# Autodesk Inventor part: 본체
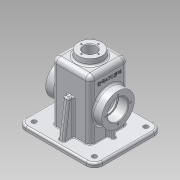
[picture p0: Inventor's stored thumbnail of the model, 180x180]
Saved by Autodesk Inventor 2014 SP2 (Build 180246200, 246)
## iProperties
Created: 2016-08
Part Number: 본체
Material: 알루미늄 6061
Document SubType Name: Modeling
Designer: user
Density: 2.71 g/cm^3
Appearance: 알루미늄 - 평지
Mass: 800.582 g
Surface Area: 913.686 cm^2
Volume: 295.418 cm^3
Author: user
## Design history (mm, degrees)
sketch "스케치1"
  geometry: L1 (-32.5, -32.5)-(32.5, -32.5); L2 (32.5, -32.5)-(32.5, 32.5); L3 (32.5, 32.5)-(-32.5, 32.5); L4 (-32.5, 32.5)-(-32.5, -32.5); L5 (-32.5, -32.5)-(32.5, 32.5); L6 (32.5, -32.5)-(-32.5, 32.5); 1 further point
  constraints: 12 end point, 2 midpoint, 2 parallel, 1 horizontal, 1 perpendicular
  dimensions: "d0" = 65 distance of L3.end L2.end; "d1" = 65 distance of L2.end L1.end
extrude "돌출1" new body sketch "스케치1" distance "d2" = 110; taper "d3" = 0 deg
feature "쉘1" dims "d4" = 5
sketch "스케치2"
  geometry: L1 (32.5, -32.5)-(-32.5, -32.5) reference; L2 (32.5, 32.5)-(32.5, -32.5) reference; L3 (-32.5, 32.5)-(32.5, 32.5) reference; L4 (-32.5, -32.5)-(-32.5, 32.5) reference; L5 (65, 57.5)-(-65, 57.5); L6 (-65, 57.5)-(-65, -57.5); L7 (-65, -57.5)-(65, -57.5); L8 (65, -57.5)-(65, 57.5); L9 (65, 57.5)-(-65, -57.5); L10 (-65, 57.5)-(65, -57.5); 1 further point
  constraints: 12 end point, 2 midpoint, 2 parallel, 1 horizontal, 1 perpendicular
  dimensions: "d5" = 130 distance of L7.end L6.end; "d6" = 115 distance of L6.end L5.end
extrude "돌출2" join sketch "스케치2" distance "d7" = 10; taper "d8" = 0 deg
sketch "스케치3"
  geometry: L1 (-65, -57.5)-(65, -57.5) reference; L2 (65, -57.5)-(65, 57.5) reference; L3 (65, 57.5)-(-65, 57.5) reference; L4 (-65, 57.5)-(-65, -57.5) reference; L5 (60, -52.5)-(-60, -52.5); L6 (-60, -52.5)-(-60, 52.5); L7 (-60, 52.5)-(60, 52.5); L8 (60, 52.5)-(60, -52.5); 1 further point
  constraints: 8 end point, 3 other
  dimensions: "d9" = 5 distance between parallel lines of L5 L1
extrude "돌출3" cut sketch "스케치3" distance "d10" = 3; taper "d11" = 0 deg
sketch "스케치4"
  geometry: C1 r 27.5 at (55, 32.5); 1 further point
  constraints: 1 centre point, 1 horizontal alignment
  dimensions: "d12" = 55 diameter of C1; "d13" = 55 distance of point (110, 32.5) C1.centre
extrude "돌출4" join sketch "스케치4" distance "d14" = 15; taper "d15" = 0 deg
sketch "스케치5"
  geometry: L1 (-27.5, 0)-(-27.5, 105) reference; L2 (-65, 10)-(65, 10) reference; L3 (-32.5, 27.5)-(-47.5, 27.5) reference; L4 (-42.5, 10)-(-42.5, 27.5); 1 further point
  constraints: 2 end point, 2 point on line, 1 perpendicular
  dimensions: "d16" = 15 distance from line of L4.start L1
feature "리브1" sketch "스케치5" dims "d17" = 1, "d18" = 6, "d19" = 0, "d20" = 0, "d21" = 1, "d22" = 1
sketch "스케치6" dims "d23" = 42
  geometry: C1 r 27.5 at (0, 0) reference; 3 further points
  constraints: 2 horizontal alignment, 1 coincident, 2 other
hole "구멍1" sketch "스케치6" at (-21, 0) diameter "d24" = 3.242; stored, may be unused: countersink angle "d28" = 90 deg, drill point angle "d30" = 118 deg; dims "d25" = 8, "d26" = 4, "d27" = 2, "d29" = 10
sketch "스케치7"
  geometry: L1 (57.5, 3)-(57.5, 10) reference; L2 (57.5, 10)-(-57.5, 10) reference; L3 (49.5, 10)-(41.068, 70); L4 (-52.5, 0)-(52.5, 0) reference; L5 (32.5, 10)-(32.5, 110) reference; L6 (41.068, 70)-(32.5, 70); 1 further point
  constraints: 4 end point, 2 point on line, 1 perpendicular
  dimensions: "d34" = 8 distance of L1.end L3.start; "d35" = 8 deg angle of L1 L3; "d36" = 70 distance from line of L4 L3.end
extrude "돌출5" join sketch "스케치7" stored distance "d37" = 10; taper "d38" = 0 deg
node "작업 평면1"
sketch "스케치8"
  geometry: C1 r 20 at (0, 0); 1 further point
  constraints: 1 centre point, 1 coincident
  dimensions: "d40" = 40 diameter of C1
extrude "돌출6" join sketch "스케치8" stored distance "d41" = 10; taper "d42" = 7 deg
hole "구멍2" diameter "d45" = 21; stored, may be unused: countersink angle "d49" = 90 deg, drill point angle "d51" = 118 deg; dims "d43" = 10, "d44" = 10, "d46" = 8, "d47" = 4, "d48" = 2, "d50" = 10
sketch "스케치9" dims "d52" = 29
  geometry: 3 further points
  constraints: 2 vertical alignment, 1 coincident, 2 other
hole "구멍3" sketch "스케치9" at (0, 14.5) diameter "d53" = 2.459; stored, may be unused: countersink angle "d57" = 90 deg, drill point angle "d59" = 118 deg; dims "d54" = 7, "d55" = 4, "d56" = 2, "d58" = 9
fillet "모깎기1" dims "d63" = 14
fillet "모깎기2" dims "d64" = 9
fillet "모깎기3" dims "d65" = 8
fillet "모깎기4" dims "d66" = 8
fillet "모깎기5" dims "d67" = 3
fillet "모깎기6" dims "d68" = 3
fillet "모깎기7" dims "d69" = 1
sketch "스케치11"
  geometry: L1 (-18, 4.5)-(-18, 44.5) reference; L2 (0, -8)-(91, -8) reference; 2 further points
  constraints: 1 other
  dimensions: "d73" = 32.5 distance from line of point (8, 24.5) L2; "d74" = 26 distance from line of point (8, 24.5) L1
feature "엠보싱1" sketch "스케치11" dims "d0" = 65, "d1" = 65, "d5" = 130, "d75" = 0.5, "d76" = 0
sketch "스케치12"
  geometry: L1 (0, 0)-(-51, 43.5); L2 (0, 0)-(51, 43.5); L3 (0, 0)-(-51, -43.5); L4 (0, 0)-(51, -43.5)
  constraints: 8 end point, 2 horizontal alignment, 2 vertical alignment, 1 collinear, 1 equal length
  dimensions: "d80" = 87 distance of L4.end L2.end; "d81" = 102 distance of L1.end L2.end
hole "구멍4" sketch "스케치12" at (-51, 43.5), (-51, -43.5), (51, -43.5), (51, 43.5) diameter "d82" = 8; stored, may be unused: countersink angle "d86" = 90 deg, drill point angle "d88" = 0 deg; dims "d83" = 7, "d84" = 4, "d85" = 2, "d87" = 9
hole "구멍5" diameter "d91" = 30; stored, may be unused: countersink angle "d95" = 90 deg, drill point angle "d97" = 0 deg; dims "d89" = 10, "d90" = 10, "d92" = 7, "d93" = 35, "d94" = 17, "d96" = 9
fillet "모깎기8" dims "d98" = 0.3
chamfer "모따기2" distance "d99" = 1; stored, may be unused: second distance "d100" = 2, angle "d101" = 45 deg
node "솔리드1"
pattern_circular "원형 패턴1" dims angle "d32" = 360 deg
mirror "대칭1"
mirror "대칭2"
pattern_circular "원형 패턴2" dims angle "d61" = 360 deg
mirror "대칭3"
